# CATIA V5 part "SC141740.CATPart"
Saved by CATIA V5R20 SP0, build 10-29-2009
Part number: SC141740
Revision: ANY
Definition: UNKNOWN
Nomenclature: SC141740
Source: Unknown
Bounding box of the stored display mesh (mm): x -5.11 to 8.803, y 0 to 17, z -40 to 0
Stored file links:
  C:\Users\Utente\Desktop\IO LAVORO\3D X SITO CF\CUMSA\3D files CG\CG 604035\SC141740.CATPart
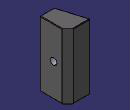
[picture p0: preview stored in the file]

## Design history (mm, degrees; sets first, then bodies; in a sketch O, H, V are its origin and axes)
Body1 "Chaflán2" (main body)
  Solid1: solid without history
